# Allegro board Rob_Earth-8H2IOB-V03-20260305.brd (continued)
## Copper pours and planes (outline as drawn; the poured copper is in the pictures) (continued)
VREG_1P2 on BOTTOM: 49.88,74.03 48.58,72.73 48.22,72.73 47.86,73.09 47.86,73.3 49.91,75.36 52.74,75.36 53.17,75.79 53.17,97.47 50.82,99.82 50.82,100.04 51.83,101.05 51.85,101.05 52.81,102.02 54.95,102.02 55.05,101.92 55.05,98.87 54.58,98.41 54.58,74.2 54.41,74.03
VREG_AMP_24P0 on BOTTOM: 85,104 91.45,104 91.95,103.5 91.95,99 92.1,98.85 96.4,98.85 96.5,98.95 96.5,105.9 96.35,106.05 85.8,106.05 85,105.25
VREG_AMP_24P0 on BOTTOM: 92.4,36.75 92.4,40.05 93.2,40.85 93.2,52.9 88.95,52.9 88.9,52.85 88.9,36.7 89,36.6 92.25,36.6
VREG_AMP_24P0 on BOTTOM: 78.25,104.05 78.25,105.25 77.45,106.05 67.05,106.05 66.8,105.8 66.8,99.15 66.85,99.1 70.35,99.1 70.97,99.72 70.97,103.47 71.5,104 78.2,104
VREG_AMP_24P0 on L3: 66.6,100.75 66.6,97.6 68.05,96.15 79.13,96.15 80.04,97.06 93.96,97.06 94.65,97.75 94.65,100.55 94.5,100.7 90.25,100.7 89.1,99.55 77.05,99.55 76.25,98.75 70.65,98.75 70.15,99.25 70.15,100.75 70,100.9 66.75,100.9
VREG_AMP_24P0 on L6: 91.82,90.82 91.82,63.3 91.05,62.53 91.05,51.05 91.2,50.9 97.8,50.9 98.09,51.19 98.09,100.36 97.75,100.7 92.45,100.7 92.3,100.55 92.3,91.3
VREG_AMP_24P0 on L6: 66.75,100.65 66.75,99.2 66.85,99.1 69.45,99.1 69.95,99.6 69.95,100.6 69.8,100.75 66.85,100.75
VREG_CAM_POC_6P7 on TOP: 23.79,81.48 25.64,81.48 26.16,82 26.16,82.84 25.54,83.46 23.95,83.46 23.65,83.16 23.65,81.62
VREG_CAM_POC_6P7 on TOP: 23.73,69.66 25.59,69.66 26.1,70.17 26.1,71.02 25.48,71.64 23.89,71.64 23.59,71.34 23.59,69.8
VREG_CAM_POC_6P7 on TOP: 23.72,92.8 25.58,92.8 26.09,93.32 26.09,94.16 25.47,94.78 23.88,94.78 23.58,94.48 23.58,92.94
VREG_CAM_POC_6P7 on TOP: 23.73,87.06 25.58,87.06 26.1,87.57 26.1,88.42 25.48,89.04 23.89,89.04 23.59,88.74 23.59,87.2
VREG_CAM_POC_6P7 on TOP: 23.75,57.05 25.6,57.05 26.12,57.56 26.12,58.41 25.5,59.03 23.91,59.03 23.61,58.73 23.61,57.19
VREG_CAM_POC_6P7 on TOP: 23.74,75.89 25.6,75.89 26.11,76.41 26.11,77.26 25.49,77.87 23.9,77.87 23.6,77.57 23.6,76.03
VREG_CAM_POC_6P7 on TOP: 28.79,101.32 28.79,99.47 29.31,98.95 30.16,98.95 30.77,99.57 30.77,101.16 30.47,101.46 28.93,101.46
VREG_CAM_POC_6P7 on TOP: 23.74,63.73 25.59,63.73 26.11,64.25 26.11,65.09 25.49,65.71 23.9,65.71 23.6,65.41 23.6,63.87
VREG_CAM_POC_6P7 on BOTTOM: 110.65,10.7 111.75,9.6 111.75,6.74 115.4,3.1 120.17,3.1 120.65,3.57 120.65,5.14 120.4,5.14 120.31,5.05 120.31,4.33 120.14,4.16 117.27,4.16 115.28,6.14 115.28,6.2 114.09,7.39 114.09,17.99 114.09,23.46 113.9,23.65 110.85,23.65 110.65,23.45
VREG_CAM_POC_6P7 on BOTTOM: 66.49,62.2 66.49,60.64 65.6,59.75 65.6,56.35 65.21,55.95 65.21,55.45 65.42,55.24 65.89,55.24 66.02,55.1 66.02,53.58 65.85,53.4 60.21,53.4 59.84,53.77 59.84,66.26 60.05,66.47 66.2,66.47 66.49,66.18 66.49,62.21
VREG_CAM_POC_6P7 on L3: 23.66,83.41 23.66,82.23 23.75,82.14 28.02,82.14 28.15,82.27 28.15,83.49 28.06,83.58 23.84,83.58
VREG_CAM_POC_6P7 on L3: 28.25,101.13 28.25,97.7 28.45,97.49 40.62,97.49 44.4,93.72 54.6,93.72 55.15,94.27 55.15,97.27 55.1,97.32 47.3,97.32 43.7,100.92 30.22,100.92 29.77,101.37 28.49,101.37
VREG_CAM_POC_6P7 on L3: 23.65,88.93 23.65,87.76 23.74,87.67 28.03,87.67 28.23,87.86 28.23,88.93 28.04,89.11 23.83,89.11
VREG_CAM_POC_6P7 on L3: 23.66,77.8 23.66,76.63 23.75,76.54 27.95,76.54 28.17,76.76 28.17,77.84 28.03,77.98 23.84,77.98
VREG_CAM_POC_6P7 on L3: 23.62,71.59 23.62,70.42 23.71,70.33 27.91,70.33 28.08,70.5 28.08,71.53 27.84,71.77 23.8,71.77
VREG_CAM_POC_6P7 on L3: 23.66,65.68 23.66,64.5 23.75,64.42 28.08,64.42 28.33,64.67 28.33,65.62 28.1,65.86 23.84,65.86
VREG_CAM_POC_6P7 on L3: 23.63,58.08 23.63,56.9 23.72,56.81 27.96,56.81 28.14,56.99 28.14,58.15 28.04,58.26 23.81,58.26
VREG_CAM_POC_6P7 on L3: 23.64,94.54 23.64,93.36 23.73,93.28 28.01,93.28 28.24,93.5 28.24,94.55 28.07,94.72 23.81,94.72
VREG_CAM_POC_6P7 on L5: 27.62,98.58 27.12,98.07 27.12,98.07 26.16,97.11 26.16,89.05 27.12,88.09 27.12,56.87 29.21,56.87 29.46,57.12 29.46,89.04 28.17,90.33 28.17,96.17 29.46,97.46 29.46,98.4 29.28,98.58
VREG_CAM_POC_6P7 on L6: 52.75,96.92 55.05,96.92 55.2,96.77 55.2,77.27 70.07,62.39 70.07,50.99 72.2,48.87 72.2,25 73.3,23.9 112.4,23.9 112.55,23.75 112.55,20.3 112.35,20.1 67.45,20.1 66.85,20.7 66.85,47.72 65.15,49.42 65.15,61.22 60.7,65.67 60.7,65.72 59.75,65.72 52.6,72.87 52.6,96.77
VREG_EDP_1P0 on BOTTOM: 53.35,41.54 53.35,44.44 53.05,44.74 50.4,44.74 49.3,43.64 49.3,41.34 49.55,41.09 52.9,41.09
VREG_EDP_1P0 on L6: 49.87,42.85 49.87,26.63 49.99,26.5 51.1,26.5 51.3,26.7 51.3,28.42 51.68,28.8 51.68,28.83 52.58,29.73 52.58,33.01 51.68,33.91 51.68,42.83 51.41,43.1 50.11,43.1
VREG_EDP_3P3 on BOTTOM: 50.15,51.81 45.28,51.81 44.9,51.43 44.9,50.74 45.45,50.19 49.82,50.19 50.27,50.64 50.27,51.69
VREG_EDP_3P3 on L3: 34.85,49.75 34.85,49.49 34.99,49.36 47.22,49.36 47.52,49.66 47.52,50.02 47.4,50.14 35.24,50.14
VREG_EDP_3P3 on L6: 46.99,50.32 46.99,49.82 47.98,48.83 47.98,47.33 47.97,47.32 47.97,47.29 48.91,46.35 48.91,37.24 48.9,37.23 48.9,36.71 49.05,36.56 49.47,36.56 49.7,36.8 49.7,46.76 48.67,47.79 48.67,49.6 47.76,50.51 47.19,50.51
VREG_FAN_12V on TOP: 181.76,8.81 181.76,8.38 181.82,8.32 182.43,8.32 182.44,8.32 182.67,8.1 182.67,6.9 182.79,6.77 183.17,6.77 183.38,6.98 183.38,8.48 182.94,8.92 181.86,8.92
VREG_FAN_12V on BOTTOM: 119.34,5.55 122.21,5.55 123.29,4.47 128.71,4.47 128.91,4.68 128.91,6.35 128.83,6.43 123.27,6.43 122.85,6.02 119.29,6.02 119.24,5.96 119.24,5.65
VREG_FAN_12V on L3: 183.15,7.72 172,7.72 171.82,7.91 168.1,7.91 167.91,7.72 145.11,7.72 144.04,8.79 135.68,8.79 134.17,7.28 128.64,7.28 128.43,7.06 128.43,6.04 128.69,5.78 134.95,5.78 136.62,7.46 143.15,7.46 144.09,6.52 183.27,6.52 183.52,6.77 183.52,7.36
VREG_FAN_12V on L6: 128.79,7.01 128.2,7.01 128.1,6.91 128.1,5.72 128.2,5.62 129,5.62 129.1,5.72 129.1,6.97 129.05,7.01 128.79,7.01
VREG_MDPX3_1P8 on TOP: 119.46,30.79 119.46,30.2 119.62,30.04 122.76,30.04 122.95,30.23 122.95,30.85 122.73,31.07 119.73,31.07
VREG_MDPX3_1P8 on TOP: 142.53,111.57 142.53,110.89 142.6,110.82 144.89,110.82 145.01,110.94 145.01,113.16 144.33,113.83 144.33,114.52 144.2,114.65 143.71,114.65 143.52,114.47 143.52,113.7 144.33,112.88 144.33,111.62 144.29,111.57 143.65,111.57 143.6,111.62 142.58,111.62
VREG_MDPX3_1P8 on TOP: 152.22,31.23 151.5,30.51 151.5,29.42 151.6,29.32 152.02,29.32 153.44,30.75 153.44,32.69 153.45,32.69 153.45,33.62 153.4,33.67 152.3,33.67 152.22,33.59
VREG_MDPX3_1P8 on BOTTOM: 111.16,90.42 111,90.42 110.95,90.37 110.95,89.87 110.53,89.45 110.06,89.45 109.91,89.31 109.91,88.8 111.02,88.8 111.22,89 111.22,90.36
VREG_MDPX3_1P8 on L3: 36.56,117.07 36.56,116.56 36.81,116.32 64.24,116.32 69.58,121.65 93.27,121.65 96.06,118.86 101.05,118.86 104.86,115.05 131.49,115.05 132.9,113.64 144,113.64 144.14,113.79 144.14,114.47 144.02,114.59 133.64,114.59 132.03,116.2 105.05,116.2 101.55,119.7 101.55,119.71 101.5,119.76 96.09,119.76 93.45,122.41 68.73,122.41 63.52,117.2 36.69,117.2
VREG_MDPX3_1P8 on L3: 121.95,30.8 131.77,30.8 131.88,30.92 131.88,31.4 131.63,31.65 122.21,31.65 121.9,31.34 121.9,30.85
VREG_MDPX3_1P8 on L3: 106.85,18.2 122.1,18.2 124.6,20.7 131.85,20.7 131.95,20.6 131.95,19.75 131.8,19.6 125.35,19.6 122.9,17.15 106.85,17.15 106.8,17.2 106.8,18.15
VREG_MDPX3_1P8 on L3: 151.99,29.98 151.49,29.98 151.32,29.81 151.32,28.2 151.43,28.08 152.06,28.08 152.21,28.24 152.21,29.76
VREG_MDPX3_1P8 on L5: 131.58,33.13 131.58,32.49 131.74,32.33 132.25,32.33 136.45,28.12 151.94,28.12 152.08,28.26 152.08,29.1 152.01,29.17 137.35,29.17 137.32,29.19 136.91,29.19 132.8,33.3 131.75,33.3
VREG_MDPX3_1P8 on L6: 133.19,114.5 132.68,114.5 132.53,114.35 132.53,95.57 130.88,93.93 130.88,52.57 130.65,52.33 130.65,34.3 130.88,34.07 130.88,8.23 131.04,8.07 131.59,8.07 131.93,8.41 131.93,32.07 132.06,32.2 132.06,34.23 132.05,34.23 132.05,34.99 131.93,35.12 131.93,57.27 131.88,57.32 131.88,93.47 133.43,95.02 133.43,114.26
VREG_MDPX3_1P8 on L7: 135.68,92.52 133.48,92.52 133.07,92.93 133.05,92.93 132.83,93.15 131.42,93.15 131.2,92.93 127.2,92.93 126.98,93.15 126.08,93.15 126.07,93.13 126.07,92.75 126.12,92.7 126.6,92.7 127.19,92.11 131.7,92.11 132.04,92.45 132.62,92.45 133.2,91.87 135.65,91.87 135.74,91.96 135.74,92.46
VREG_MDPX3_1P8 on L7: 128.6,97.5 135.53,97.5 135.78,97.25 135.78,96.82 135.69,96.73 135.26,96.73 135.09,96.9 133.08,96.9 133.03,96.84 128.6,96.84 128.55,96.89 128.55,97.45
VREG_NVME_3P3 on TOP: 130.01,48.85 130.01,47.58 130.22,47.36 130.66,47.36 130.71,47.42 130.71,48.8 130.62,48.89 130.05,48.89
VREG_NVME_3P3 on TOP: 126.19,36.69 126.19,35.17 126.25,35.12 127.05,35.12 127.12,35.19 127.12,36.66 126.99,36.78 126.29,36.78
VREG_NVME_3P3 on TOP: 126.86,48.86 126.86,47.18 127.03,47.01 127.62,47.01 127.67,47.06 127.67,48.71 127.49,48.89 126.89,48.89
VREG_NVME_3P3 on BOTTOM: 163.64,46.99 161.67,46.99 161.18,46.5 161.18,43.87 161.44,43.61 164.65,43.61 165.3,44.26 165.3,46.36 164.65,47.01 163.66,47.01
VREG_NVME_3P3 on BOTTOM: 146.58,43.65 146.58,47.26 146.9,47.57 149.1,47.57 149.27,47.41 149.27,46 148.49,45.22 148.49,43.59 148.43,43.52 146.71,43.52
VREG_NVME_3P3 on BOTTOM: 145.5,47.61 142.69,47.61 142.44,47.35 142.44,43.97 142.88,43.53 144.85,43.53 144.93,43.61 144.93,46.24 145.6,46.9 145.6,47.5
VREG_NVME_3P3 on L3: 162.76,48.27 145.42,48.27 145.23,48.09 145.23,47.09 146.7,45.62 162.75,45.62 163.15,46.02 163.15,47.88
VREG_NVME_3P3 on L3: 125.36,48.87 125.81,48.41 127.05,48.41 127.35,48.11 130.41,48.11 130.63,48.32 130.63,48.63 130.16,49.09 127.77,49.09 127.47,49.39 125.5,49.39 125.36,49.24
VREG_NVME_3P3 on L3: 125.7,35.51 125.7,35.01 125.75,34.96 127.08,34.96 127.25,35.14 127.25,35.55 127.1,35.7 125.88,35.7
VREG_NVME_3P3 on L5: 143.25,35.16 161.8,35.16 162.12,35.48 162.14,35.48 162.14,35.84 161.88,36.1 125.63,36.1 125.55,36.02 125.55,34.92 125.68,34.78 142.87,34.78
VREG_NVME_3P3 on L6: 146.91,48.01 146.91,46.87 147.05,46.73 148.28,46.73 148.8,47.25 148.8,48.07 148.67,48.21 147.11,48.21
VREG_NVME_3P3 on L6: 125.87,49.14 125.23,49.14 125.01,48.92 125.01,35.16 125.33,34.85 126.27,34.85 126.58,35.16 126.58,35.25 125.95,35.88 125.95,36.34 125.98,36.37 125.98,49.03
VREG_NVME_3P3 on L6: 162.35,47.4 162.98,47.4 163.02,47.36 163.02,46.84 162.02,45.83 162.02,35.26 161.87,35.12 161.38,35.12 161.26,35.24 161.26,46.31
VREG_NVME_3P3 on L6: 145.17,46.9 146.04,46.9 146.08,46.94 146.08,48.1 146.01,48.16 145.28,48.16 145,47.88 145,47.07
VREG_SUB_1P8 on BOTTOM: 74.2,96.78 75.85,96.78 75.98,96.64 75.98,96.2 75.83,96.05 74.2,96.05 74.15,96.1 74.15,96.73
VREG_SUB_1P8 on BOTTOM: 54.89,110.55 54.99,110.45 54.99,103.36 54.95,103.32 52.05,103.32 49.7,105.67 47.6,105.67 47.55,105.72 47.55,107.87 50.23,110.55
VREG_SUB_1P8 on L4: 52.8,97.75 54.45,97.75 55.1,97.1 71.95,97.1 73.15,95.9 86.75,95.9 87.2,96.35 87.2,97.8 86.85,98.15 73.6,98.15 72.95,98.8 55.45,98.8 55.05,99.2 52.75,99.2 52.7,99.15 52.7,97.85
VREG_SUB_1P8 on L6: 52.95,104.12 53.15,104.32 53.95,104.32 54,104.27 54,97.87 53.95,97.82 53.1,97.82 52.95,97.97
VREG_SUB_3P3 on TOP: 139.25,89.82 141.95,89.82 142.05,89.92 142.05,93.17 141.75,93.47 140,93.47 139.95,93.42 139.95,92.12 139.25,91.42
VREG_SUB_3P3 on TOP: 152.25,38.06 152.25,36.53 152.26,36.53 152.26,35.63 153.64,34.24 153.64,30.76 151.75,28.87 150.92,28.87 150.84,28.79 150.84,28.31 150.94,28.21 152.18,28.21 154.75,30.78 154.75,36.73 153.33,38.15 152.34,38.15
VREG_SUB_3P3 on TOP: 136.27,27.25 136.27,26.92 136.45,26.75 138.56,26.75 138.69,26.87 138.69,27.17 138.54,27.32 136.34,27.32
VREG_SUB_3P3 on TOP: 126.27,38.1 128.24,38.1 128.34,38.2 128.34,39.17 128.05,39.46 126.39,39.46 126.13,39.2 126.13,38.24
VREG_SUB_3P3 on TOP: 40.77,120.3 39.15,120.3 38.93,120.08 38.93,116.28 39.58,115.63 41.16,115.63 41.4,115.86 41.4,116.93 41.03,117.3 41.03,120.05
VREG_SUB_3P3 on TOP: 101.75,92.62 101.65,92.52 101.65,90.34 101.85,90.14 105.05,90.14 105.05,90.15 106,90.15 106.1,90.25 106.1,92.55 106.03,92.62
VREG_SUB_3P3 on BOTTOM: 124.08,112.13 123.22,112.13 123.08,112.26 122.29,112.26 122.19,112.37 122.19,113.1 122.29,113.21 124.09,113.21 124.18,113.12 124.18,112.23
VREG_SUB_3P3 on BOTTOM: 116.5,112.2 115.63,112.2 115.5,112.34 114.71,112.34 114.61,112.44 114.61,113.18 114.71,113.28 116.51,113.28 116.6,113.19 116.6,112.31
VREG_SUB_3P3 on BOTTOM: 104.35,89 98.45,89 98.3,89.15 98.3,92.95 98.35,93 104.55,93 104.55,89.2
VREG_SUB_3P3 on BOTTOM: 132.3,112.18 131.44,112.18 131.31,112.31 130.52,112.31 130.42,112.42 130.42,113.16 130.52,113.26 132.32,113.26 132.41,113.17 132.41,112.29
VREG_SUB_3P3 on BOTTOM: 109.26,112.19 108.4,112.19 108.26,112.32 107.47,112.32 107.37,112.43 107.37,113.16 107.47,113.27 109.27,113.27 109.36,113.18 109.36,112.29
VREG_SUB_3P3 on BOTTOM: 53.88,51.83 51.68,51.83 51.56,51.71 51.56,51.19 51.72,51.03 54.78,51.03 54.82,51.07 54.82,51.72 54.72,51.82 53.9,51.82
VREG_SUB_3P3 on BOTTOM: 55.32,40.39 55.21,40.51 55.21,43.11 55.27,43.17 56.8,43.17 57.2,42.77 57.2,40.47 57.12,40.39
VREG_SUB_3P3 on BOTTOM: 54.74,65.25 54.74,62.73 54.88,62.59 55.09,62.59 55.48,62.98 55.48,64.13 55.48,65.28 55.4,65.36 54.86,65.36
VREG_SUB_3P3 on BOTTOM: 55.79,113.79 55.79,112.92 55.67,112.8 52.83,112.8 52.77,112.85 52.77,113.95 52.82,114 55.57,114
VREG_SUB_3P3 on L3: 95.13,92.8 95.13,90.92 95.48,90.57 128.6,90.57 130.55,92.52 138.45,92.52 139.5,91.47 141.9,91.47 142.05,91.62 142.05,93.17 141.55,93.67 129.35,93.67 128.4,92.72 105.81,92.72 104.51,94.01 102.72,94.01 101.78,93.07 95.4,93.07
VREG_SUB_3P3 on L3: 128.68,25.48 128.68,25 128.75,24.93 136.76,24.93 138.55,26.72 138.55,27.17 138.5,27.22 138.16,27.22 136.6,25.65 128.85,25.65
VREG_SUB_3P3 on L3: 39.37,117.34 63.49,117.34 68.72,122.57 93.45,122.57 96.14,119.89 101.51,119.89 105.04,116.36 135.13,116.36 135.5,116.73 135.5,119.09 134.41,120.18 107.26,120.18 104.22,123.23 99.1,123.23 96.56,125.76 67.23,125.76 62.04,120.58 39.23,120.58 39.04,120.39 39.04,117.67
VREG_SUB_3P3 on L3: 101.56,64.05 54.86,64.05 54.77,63.96 54.77,63.46 55.24,63 101.61,63 101.79,63.19 101.79,63.81
VREG_SUB_3P3 on L3: 125.25,38.52 125.25,37.83 125.38,37.7 128.23,37.7 128.45,37.92 128.45,38.71 128.4,38.77 127.9,38.77 127.8,38.67 125.4,38.67
VREG_SUB_3P3 on L3: 128.59,30.65 128.59,30.07 128.7,29.96 132.16,29.96 132.18,29.98 132.4,29.98 134.25,28.13 150.97,28.13 151.14,28.29 151.14,28.98 150.95,29.16 134.56,29.16 132.95,30.77 128.71,30.77
VREG_SUB_3P3 on L3: 128.14,64.87 102.83,64.87 102.29,65.41 102.29,67.33 102.98,68.01 128.22,68.01 128.5,67.73 128.5,65.23
VREG_SUB_3P3 on L6: 107.58,112.97 107.58,116.72 107.79,116.93 108.48,116.93 108.65,116.75 108.65,113.27 108.27,112.88 107.66,112.88
VREG_SUB_3P3 on L6: 43.75,111.75 43.96,111.97 43.96,118.72 43.88,118.81 43.02,118.81 42.95,118.74 42.95,111.97 43.17,111.75
VREG_SUB_3P3 on L6: 52.85,113.32 52.85,118.37 53.1,118.62 54.55,118.62 54.7,118.47 54.7,113.37 54.55,113.22 52.95,113.22
VREG_SUB_3P3 on L6: 122.3,112.91 122.3,116.66 122.51,116.87 123.2,116.87 123.37,116.7 123.37,107.47 125.05,105.79 125.05,101.15 125,101.1 124.2,101.1 124.12,101.18 124.12,105.67 122.75,107.04 122.75,112.46
VREG_SUB_3P3 on L6: 131.46,116.91 131.64,116.74 131.64,108.76 131.25,108.37 131.25,101.7 131.15,101.6 130.65,101.6 130.5,101.75 130.5,112.2 130.1,112.6 130.1,116.85 130.16,116.91
VREG_SUB_3P3 on L6: 55.38,65.13 55.38,63.86 55.59,63.65 55.59,44.97 56.9,43.65 56.9,42.9 56.79,42.78 56.21,42.78 54.46,44.54 54.46,65.22 54.6,65.37 55.13,65.37
VREG_SUB_3P3 on L6: 114.64,112.99 114.64,116.73 114.85,116.94 115.55,116.94 115.72,116.77 115.72,113.28 115.34,112.9 114.73,112.9
VREG_SUB_3P3 on L6: 126.24,36.29 126.24,13.92 127.41,12.75 128.55,12.75 129.24,13.44 129.24,50.09 129.47,50.33 129.47,66.1 128.58,66.99 126.16,66.99 125.97,66.8 125.97,66.23 125.97,58.81 125.97,36.56
VREG_SUB_3P3 on L6: 104.87,119.3 102.36,119.3 101.1,118.03 101.1,103.4 100.45,102.75 100.45,67.65 101.14,66.96 101.14,63.07 101.38,62.83 104.33,62.83 104.7,63.2 104.7,74.07 104.73,74.09 104.73,93.72 104.45,94 104.45,101.82 104.73,102.1 104.73,116.46 105.59,117.32 105.59,118.58
VREG_SUB_5P0 on TOP: 140.07,107.97 138.79,107.97 138.58,107.76 138.58,106.17 138.93,105.82 140.11,105.82 140.27,105.98 140.27,107.77
VREG_SUB_5P0 on TOP: 151.71,113.49 149.7,113.49 149.64,113.44 149.64,112.13 149.81,111.96 151.76,111.96 151.88,112.08 151.88,113.33
VREG_SUB_5P0 on TOP: 163.97,120.1 163.97,119.12 164.11,118.98 166.08,118.98 166.21,119.11 166.21,120.12 165.89,120.44 164.32,120.44
VREG_SUB_5P0 on TOP: 150.01,104.72 150.01,102.4 150.11,102.29 151.21,102.29 151.44,102.52 151.44,104.59 151.26,104.77 150.06,104.77
VREG_SUB_5P0 on BOTTOM: 51.65,56.55 51.51,56.41 51.51,55.58 51.7,55.39 54.05,55.39 54.31,55.65 54.31,56.33 54.09,56.55
VREG_SUB_5P0 on BOTTOM: 120.95,79.4 120.95,70.58 122.51,69.01 122.51,58.41 123.54,57.38 123.54,54.72 123.64,54.61 124.5,54.61 125.01,55.12 125.01,55.85 127.39,58.22 127.39,58.86 128.64,60.12 133.95,60.12 136.5,62.67 136.95,62.67 137.05,62.77 137.05,64.67 137,64.72 135.6,64.72 135.45,64.57 135.45,63.17 133.35,61.07 131.65,61.07 131.5,61.22 131.5,62.32 131.85,62.67 132.61,62.67 132.75,62.82 132.75,63.69 132.62,63.82 132.62,64.68 132.4,64.9 130.33,64.9 129.96,65.28 129.96,67.74 128.85,68.85 128.85,79.68 128.68,79.85 121.39,79.85
VREG_SUB_5P0 on L3: 149.14,117.56 149.14,116.25 149.38,116.01 150,116.01 150.48,116.5 156.59,116.5 159.59,119.49 164.49,119.49 165.07,118.91 166.02,118.91 166.5,119.4 166.5,120.12 166.13,120.49 158.69,120.49 156.13,117.93 152.36,117.93 152.35,117.92 149.51,117.92
VREG_SUB_5P0 on L3: 127.93,81.41 125.02,81.41 124.73,81.13 124.73,79.73 125.1,79.37 127.89,79.37 128.09,79.57 128.09,81.25
VREG_SUB_5P0 on L3: 49.59,57.46 119.22,57.46 119.37,57.31 120.11,57.31 120.8,58 123.21,58 123.49,57.71 123.49,57.29 123.26,57.06 121.05,57.06 120.54,56.55 118.8,56.55 118.68,56.67 49.66,56.67 49.4,56.94 49.4,57.27
VREG_SUB_5P0 on L3: 139.35,108.02 123.88,108.02 123.76,107.91 123.76,107.3 124.08,106.98 139.34,106.98 139.5,107.15 139.5,107.87
VREG_SUB_5P0 on L3: 151.78,113.13 149.21,113.13 149.03,112.96 149.03,112.13 149.23,111.94 151.78,111.94 151.92,112.07 151.92,112.99
VREG_SUB_5P0 on L3: 149.28,102.7 149.16,102.58 149.16,101.95 149.29,101.82 151.2,101.82 151.29,101.91 151.29,102.63 151.22,102.7
VREG_SUB_5P0 on L3: 128.31,97.92 149.75,97.92 150.1,98.27 150.1,99.13 149.87,99.35 129.83,99.35 128.78,100.41 125.11,100.41 124.84,100.14 124.84,98.54 125.1,98.28 127.96,98.28
VREG_SUB_5P0 on L5: 125.47,98.22 136.4,98.22 137.24,99.06 137.24,100.38 136.94,100.68 125.38,100.68 125.12,100.41 125.12,98.57
VREG_SUB_5P0 on L6: 122.7,59.57 122.7,57.92 122.43,57.65 122.43,57.16 122.54,57.05 123.38,57.05 123.56,57.23 123.56,59.44 123.34,59.66 122.79,59.66
VREG_SUB_5P0 on L6: 53.3,56.11 53.3,57.23 53.41,57.35 54.12,57.35 54.24,57.23 54.24,56.09 54.22,56.06 53.34,56.06
VREG_SUB_5P0 on L6: 125.04,78.51 127.96,78.51 128.44,78.99 128.44,97.35 128.44,97.35 128.44,100.4 128.15,100.69 124.18,100.69 123.99,100.5 123.99,97.52 123.05,96.58 123.05,80.5
VREG_SUB_5P0 on L6: 149.38,110.4 149.38,107.78 149.12,107.52 149.12,99.62 149.11,99.61 149.11,98.43 149.26,98.27 149.93,98.27 150.19,98.53 150.19,99.71 150.27,99.78 150.27,107.44 150.55,107.73 150.55,111.25 150.27,111.54 150.27,117.12 150.14,117.25 149.28,117.25 149.07,117.04 149.07,110.71
VREG_SUB_5P0 on L6: 136.05,107.6 136.05,99.65 136.23,99.47 136.98,99.47 137.23,99.72 137.23,107.86 137.11,107.97 136.42,107.97
VREG_SW_A_1P8 on BOTTOM: 46.2,105.62 46.2,106.77 45.95,107.02 36.55,107.02 35.6,106.07 35.6,105.92 36.7,104.82 37.5,105.62
VREG_SW_A_1P8 on L6: 36.4,106.57 37.55,106.57 37.6,106.52 37.6,105.82 37.55,105.77 36.35,105.77 36.3,105.82 36.3,106.47
N22883753 on BOTTOM: 18.99,57.5 18.99,54.26 20.08,53.17 22.36,53.17 22.45,53.26 22.45,53.65 22.26,53.84 21.94,53.84 21.62,54.17 21.62,57.61 21.32,57.9 19.39,57.9
N23918883 on BOTTOM: 126.03,27.73 135.32,27.73 135.65,27.4 135.65,25.3 136,24.95 142.75,24.95 143.05,25.25 143.05,33.15 142.6,33.6 126,33.6 126,27.75
N23919030 on TOP: 167.64,11.37 167.64,20.03 167.35,20.32 150.8,20.32 144.84,26.28 131.26,26.28 130.87,25.89 130.87,20.5 133.19,18.18 138.92,18.18 147.54,9.57 165.84,9.57
N23919030 on BOTTOM: 175.6,16.84 170.52,16.84 169.1,18.26 164.1,18.26 163.8,17.96 163.8,9.85 164.26,9.39 174.75,9.39 175.95,10.59 175.95,16.49
N23919032 on TOP: 175.69,20.43 169.29,20.43 168.64,19.78 168.64,12.13 169.94,10.83 174.89,10.83 176.09,12.03 176.09,20.03
N25173690 on BOTTOM: 17.2,62.82 18.53,62.82 18.73,62.63 18.73,61.3 19.04,60.99 20.29,60.99 20.37,61.08 20.37,64.7 20.73,65.05 20.97,65.05 21.07,65.15 21.07,65.78 21.05,65.81 19.02,65.81 17.2,63.99
N25174282 on BOTTOM: 18.55,79.07 16.6,79.07 16.01,78.48 16.01,74.25 16.42,73.85 16.86,73.85 16.95,73.75 16.95,72.57 17.13,72.4 17.72,72.4 17.94,72.61 17.94,76.63 17.92,76.64 17.92,78.22 18.11,78.41 18.53,78.41 18.61,78.49 18.61,79
N25174453 on BOTTOM: 18.46,66.29 18.46,68.33 20.37,70.23 21.84,70.23 21.95,70.12 21.95,66.56 22.2,66.32 22.44,66.32 22.7,66.05 22.7,65.44 22.66,65.39 22.18,65.39 22.13,65.45 22.13,65.88 21.92,66.08 18.67,66.08
N25176689 on BOTTOM: 40.75,64.92 40.7,64.92 40.4,64.62 40.4,64.47 43.59,61.28 43.88,61.28 44.44,61.83 44.44,62.02 44.1,62.36 43.75,62.36 41.05,65.07 40.9,65.07
N25187975 on BOTTOM: 54.43,62.62 54.43,66.72 53.78,66.72 53.63,66.57 53.63,64.52 54.03,64.12 54.03,62.67 54.13,62.57 54.38,62.57
N25264597 on BOTTOM: 17.4,97.16 17.4,101.68 18.06,102.34 20.49,102.34 20.76,102.07 20.76,101.71 20.05,101 20.01,101 20,100.99 20,97.37 19.72,97.08 17.48,97.08
N25264985 on BOTTOM: 49.78,90.22 50.1,90.54 50.1,91.24 49.99,91.35 49.28,91.35 49.04,91.1 44.09,91.1 43.65,90.67 43.65,90.49 43.92,90.22
N25265127 on BOTTOM: 18.81,92.84 18.81,91 19.64,90.17 21.23,90.17 21.52,89.88 21.52,89.47 21.65,89.33 22.1,89.33 22.15,89.38 22.15,89.87 21.51,90.52 21.5,90.52 21.45,90.56 21.45,93.96 21.32,94.1 20.08,94.1
N25265806 on BOTTOM: 18.69,82.44 18.69,80.15 20.4,78.43 20.89,78.43 21.36,77.96 21.36,77.42 21.41,77.38 22.24,77.38 22.28,77.41 22.28,77.92 21.44,78.76 21.31,78.76 21.25,78.82 21.25,79.87 21.26,79.88 21.26,82.1 20.81,82.55 18.79,82.55
N25532507 on BOTTOM: 92.06,62.92 92.06,64.16 92.43,64.52 92.43,66.08 91.65,66.86 91.65,68.47 91.91,68.73 91.91,70.03 91.86,70.08 91.65,70.08 91.59,70.03 91.59,68.83 91.35,68.59 91.35,64.96 90.98,64.59 90.98,58.52 91.2,58.3 110,58.3 113.15,55.15 113.15,50.85 113.4,50.6 118.8,50.6 119.2,51 119.2,56.25 117.9,57.55 117.9,62.5 117.8,62.6 92.38,62.6
N25532700 on BOTTOM: 95.5,80.1 95.5,79.04 95.64,78.9 96.12,78.9 98.82,76.2 98.82,75.59 99.09,75.32 101.41,75.32 103.63,73.1 111.21,73.1 111.56,73.46 111.56,77.68 111.28,77.96 106.45,77.96 104.02,80.4 95.8,80.4
N25532835 on BOTTOM: 113.94,62.92 120.78,62.92 121.66,63.79 121.66,68.68 120.3,70.04 114.31,70.04 113.94,69.67
N25532881 on BOTTOM: 99.8,87.15 99.8,83.1 100,82.9 105.38,82.9 106.5,84.02 111.47,84.02 111.5,84.05 111.5,87.95 111.43,88.03 100.68,88.03
N25533068 on BOTTOM: 94.06,74.61 94.06,73.86 94.16,73.76 99.46,73.76 99.71,74.01 99.71,74.8 99.57,74.94 98.35,74.94 98.11,74.71 94.16,74.71
N25637659 on BOTTOM: 84.3,104.05 84.3,106.6 86.6,108.9 88.35,108.9 88.9,109.45 88.9,109.9 89.8,110.8 89.8,112.9 90.3,113.4 95.05,113.4 95.15,113.3 95.15,109.75 91.75,106.35 85.7,106.35 84.75,105.4 84.75,104.05
N25637825 on BOTTOM: 82.35,104.05 82.35,108.4 83.1,109.15 83.1,112.95 83.55,113.4 87.45,113.4 87.85,113 87.85,110.7 87,109.85 86.7,109.85 82.8,105.95 82.8,104.05
N25637889 on BOTTOM: 80.9,104.05 80.9,108.4 80.1,109.2 80.1,112.95 79.65,113.4 75.35,113.4 75.2,113.25 75.2,111.1 80.45,105.85 80.45,104.05
N26057360 on TOP: 136.69,111.47 136.69,109.82 136.89,109.62 139.19,109.62 139.59,110.02 139.59,110.68 139.72,110.8 141.58,110.8 141.65,110.88 141.65,111.51 141.59,111.57 136.79,111.57
N26101041 on BOTTOM: 83.05,56.39 78.27,56.39 75.56,53.68 71.25,53.68 71.16,53.59 71.16,53.39 71.24,53.31 76.62,53.31 77.27,52.67 86.05,52.67 86.3,52.92 86.3,56.28 86.2,56.38 83.06,56.38
N26101344 on BOTTOM: 71.52,60.34 71.52,70.17 71.17,70.51 67.34,70.51 66.82,70 66.82,61.24 68.14,59.92 68.14,59.41 68.24,59.31 70.5,59.31
N26865506 on TOP: 129.68,8.56 128.67,8.56 128.6,8.48 128.6,7.6 128.78,7.42 131.66,7.42 131.74,7.49 131.74,8.09 131.59,8.23 130,8.23
N26877401 on TOP: 29.96,121.45 29.96,124.9 30.01,124.95 30.01,126.05 29.96,126.1 29.31,126.1 29.26,126.05 29.26,121.5 29.36,121.4 29.91,121.4
N26878490 on TOP: 47.81,121.32 48.31,121.32 48.46,121.47 48.46,125.87 48.31,126.02 47.91,126.02 47.66,125.77 47.66,121.47
N26907161 on TOP: 135.47,104.72 135.47,104.1 135.59,103.98 136.23,103.98 136.42,104.17 137.09,104.17 137.19,104.26 137.19,104.67 137.15,104.72
N26907165 on TOP: 129.53,104.93 129.53,104.88 129.68,104.73 129.68,104.1 129.78,104 130.4,104 130.53,104.13 131.34,104.13 131.42,104.22 131.42,104.77 131.12,105.07 129.67,105.07
N28338469 on BOTTOM: 20.48,89.86 18.24,89.86 17.25,88.87 17.25,86.44 18.61,85.08 19.78,85.08 19.93,85.23 19.93,89.08 20.18,89.33 20.51,89.33 20.56,89.38 20.56,89.77
N28694569 on BOTTOM: 55.05,40.54 55.05,44.34 54.8,44.59 54.15,44.59 54.05,44.49 54.05,42.54 54.7,41.89 54.7,40.54 54.8,40.44 54.95,40.44
N29156376 on BOTTOM: 143.15,23.55 143.15,20.45 140.75,18.05 140.75,16.65 140.65,16.55 139.7,16.55 139.7,19.25 138.65,20.3 137.3,20.3 137.2,20.4 137.2,24.25 137.25,24.3 140.15,24.3 140.85,23.6 143.1,23.6
N29318624 on BOTTOM (solid shape): outline of 115 points within 189.42,42.05 191.32,43.45
N29318627 on BOTTOM (solid shape): outline of 115 points within 189.42,64 191.32,65.41
N29318651 on BOTTOM (solid shape): outline of 115 points within 189.42,40.05 191.32,41.45
N29318675 on BOTTOM (solid shape): outline of 115 points within 189.42,62.01 191.32,63.41
N29438820 on TOP: 155.62,41.66 155.62,37.69 156.34,36.98 159.75,36.98 160.71,37.94 160.71,41.55 160.18,42.08 156.04,42.08
N29438820 on TOP: 178.98,126.92 178.98,126.11 179.29,125.8 187.68,125.8 188.07,126.2 188.07,127.58 187.97,127.69 178.39,127.69 178.35,127.65 178.35,127.1 178.4,127.05 178.85,127.05
N29438820 on L3: 159.97,127.18 159.97,125.74 160.21,125.5 180.91,125.5 181.66,126.25 181.66,127.31 181.08,127.9 160.69,127.9
N29438820 on L3: 158.75,43.16 158.75,41.15 159.04,40.86 160.93,40.86 161.13,41.06 161.13,42.91 160.72,43.32 158.91,43.32
N29438820 on L6: 160.33,119.4 160.33,48.94 158.9,47.51 158.9,41.96 159.06,41.8 160.98,41.8 161.11,41.93 161.11,46.35 162.61,47.85 162.61,74.4 163.2,74.99 163.2,120.15 162.61,120.74 162.61,126.7 162.19,127.11 160.6,127.11 160.59,127.11 160.06,127.11 160,127.05 160,119.73
N29453895 on BOTTOM: 55.54,112.6 51.39,112.6 51.09,112.3 51.09,111.3 51.19,111.2 53.14,111.2 54.19,112.25 55.54,112.25 55.64,112.35 55.64,112.5
N29503777 on BOTTOM: 101.5,18.85 98.7,18.85 97.6,19.95 96.35,19.95 96.3,20 96.3,21.1 96.35,21.15 98.05,21.15 99.9,19.3 101.5,19.3
N29949460 on BOTTOM: 95.95,21.2 95.95,20.55 95.85,20.45 91.05,20.45 90.75,20.75 90.75,25.25 90.8,25.3 94.35,25.3 94.4,25.25 94.4,22.75
N30232657 on BOTTOM: 78.95,104.05 78.95,106.45 76.5,108.9 74.65,108.9 74.4,109.15 74.4,111 72,113.4 68.05,113.4 67.95,113.3 67.95,110.05 71.7,106.3 77.55,106.3 78.5,105.35 78.5,104.05
N30564201 on TOP: 145.06,57.35 143.88,57.35 141.67,55.13 139.91,55.13 139.7,54.92 139.7,51.6 139.75,51.55 140.2,51.55 140.28,51.63 140.28,54.15 140.62,54.49 141.95,54.49 143.22,55.76 145.16,55.76 145.37,55.97 145.37,57.04
N30676950 on TOP: 129.08,76.19 128.57,76.19 128.17,75.79 128.17,74.47 128.29,74.36 129.16,74.36 129.3,74.5 129.3,75.11 129.14,75.26 129.14,76.13
N30853432 on TOP: 90.9,114.15 87.48,114.15 87.35,114.03 87.35,113.04 88.48,111.91 90.49,111.91 91.07,112.49 91.07,113.98
N31297683 on BOTTOM: 132.82,97.35 131.89,97.35 131.84,97.31 131.84,96.68 131.75,96.59 131.15,96.59 131.06,96.5 131.06,96.08 131.17,95.97 132.24,95.97 132.26,95.95 132.5,95.95 132.88,96.34 132.88,97.29
N31298259 on BOTTOM: 111.2,90.95 111.2,91.85 110.65,91.85 110.07,91.27 110.07,90.93 110.13,90.87 111.12,90.87
N31300206 on BOTTOM: 126.77,97.45 125.57,97.45 125.23,97.11 125.23,96.19 125.33,96.09 126.64,96.09 126.9,96.35 126.9,97.33
N31982835 on BOTTOM: 101.4,54.65 101.4,41.4 101.5,41.3 104.65,41.3 104.8,41.45 104.8,54.65
N32250526 on BOTTOM: 122.57,6.56 119.1,6.56 118.65,7.02 118.65,13.59 118.23,14 116.35,14 115.96,13.61 115.96,7.88 117.69,6.15 122.55,6.15 122.65,6.25 122.65,6.48
N32254929 on TOP: 139.32,89.56 142.95,89.56 143.1,89.41 143.1,88.56 141.32,88.56 140.67,89.21 139.32,89.21 139.22,89.31 139.22,89.46

Small or netless copper shapes (teardrops, artwork), in the pictures only: 2 on BOTTOM, 1 on TOP, 14 on L6

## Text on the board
Ref Des/Silkscreen Top: J3501 | J3500 | SPK_R | SPK_L | L | CAN3 | H | SW3300 | CAN2 | CAN1 | CAN0 | 10 | P2 | 11 | A2 | A1 | P1 | 38 | 39 | 36 | 37 | J3400 | 19 | TP | 18 | 17 | 15 | 16 | 13 | 14 | G | 1.8 | 3.3 | 20 | 1 | GND | FAN2 | FAN1 | Ethernet/USB2.0 | Ethernet/USB3.0 | DC | 12~24V | View | Front | CSI1 | CSI0 | B | C | CH2_CLK | D | A | CH2_DATA | CH1_CLK | CH1_DATA | EtherCAT | HDMI_3 | HDMI_1 | HDMI_2 | CH4_CLK | CH4_DATA | CH3_CLK | CH3_DATA | CAN3 OFF | ON | CAN2 OFF | CAN1 OFF | CAN0 OFF | RS485 OFF | RS_485_B | RS_485_A | RS_232_RX | RS_232_TX | RION IO Board-DVT
User.17: FIGURE | FINISHED_SIZE | 0.1 | DRILL CHART: TOP to L2 | ALL UNITS ARE IN MILLIMETERS | PLATED | NONSTANDARD | LASER | QTY | 1067
User.18: FIGURE | FINISHED_SIZE | 0.25 | 0.55 | 0.65 | 0.9 | 1.0 | 1.02 | 1.5 | 1.6 | 1.8 | 2.2 | 2.8 | 1.1 | 1.22 | 1.25 | 1.7 | 3.0 | 3.2 | 2.3x1.0 | 2.7x0.9 | 1.8x0.8 | DRILL CHART: TOP to BOTTOM | ALL UNITS ARE IN MILLIMETERS | PLATED | NON-PLATED | NONSTANDARD | - | QTY | 976 | 57 | 8 | 10 | 4 | 128 | 2 | 12 | 17 | 1 | 7 | 16
User.19: FIGURE | FINISHED_SIZE | 0.1 | DRILL CHART: L2 to L3 | ALL UNITS ARE IN MILLIMETERS | PLATED | NONSTANDARD | LASER | QTY | 17
User.20: FIGURE | FINISHED_SIZE | 0.2 | DRILL CHART: L3 to L6 | ALL UNITS ARE IN MILLIMETERS | PLATED | NONSTANDARD | - | QTY | 6793
User.21: FIGURE | FINISHED_SIZE | 0.1 | DRILL CHART: L6 to L7 | ALL UNITS ARE IN MILLIMETERS | PLATED | NONSTANDARD | LASER | QTY | 53
User.22: FIGURE | FINISHED_SIZE | 0.1 | DRILL CHART: L7 to BOTTOM | ALL UNITS ARE IN MILLIMETERS | PLATED | NONSTANDARD | LASER | QTY | 1684
User.23: FIGURE | FINISHED_SIZE | 0.1 | DRILL CHART: L6 to BOTTOM | ALL UNITS ARE IN MILLIMETERS | PLATED | NONSTANDARD | LASER | QTY | 170 | 8812
User.24: FIGURE | FINISHED_SIZE | 0.1 | DRILL CHART: TOP to L3 | ALL UNITS ARE IN MILLIMETERS | PLATED | NONSTANDARD | LASER | QTY | 9906
